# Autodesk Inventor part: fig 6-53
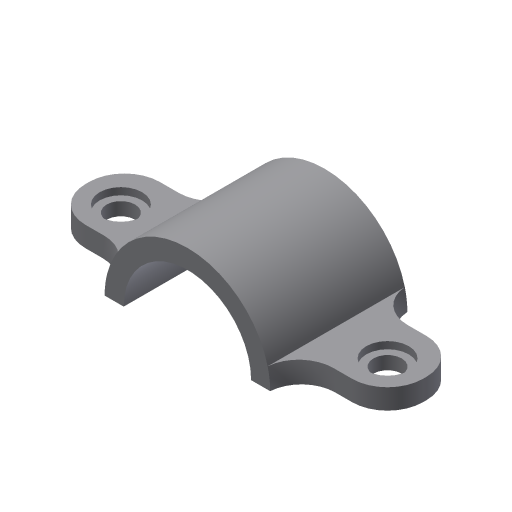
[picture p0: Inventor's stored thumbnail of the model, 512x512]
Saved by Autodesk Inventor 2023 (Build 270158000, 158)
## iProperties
Created: 2004-05
Part Number: fig 6-53
Document SubType Name: Modeling
Designer: CADCIM Technologies
Manufacturer: Standard
Standards Organization: Custom
Density: 1 g/cm^3
Material: Generic
Appearance: Default
Author: CADCIM Technologies
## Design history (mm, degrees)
node "Sketch1"
sketch "Sketch2"
  geometry: L1 (23.378, 0)-(17.996, 0); L2 (-17.996, 0)-(-23.378, 0); A1 r 23.378 centre (0, 0) between (23.378, 0) and (-23.378, 0); A2 r 17.996 centre (0, 0) between (17.996, 0) and (-17.996, 0)
  constraints: 4 end point, 4 point on circle, 2 centre point, 1 collinear, 1 horizontal
extrude "Extrusion1" new body sketch "Sketch2" stored distance "d0" = 38.75; taper "d1" = 0 deg
sketch "Sketch3"
  geometry: L1 (23.378, 0)-(17.996, 0); L2 (-17.996, 0)-(-23.378, 0) reference; L3 (-23.378, 0)-(-47.662, 0); L4 (-47.662, 0)-(-47.662, 5.722); L5 (-47.662, 5.722)-(-22.667, 5.722); A1 r 17.996 centre (0, 0) between (17.996, 0) and (-17.996, 0) reference; A2 r 23.378 centre (0, 0) between (23.378, 0) and (-23.378, 0) reference; 1 further point
  constraints: 10 end point, 5 point on circle, 2 centre point, 1 collinear, 1 horizontal, 1 midpoint, 1 parallel, 1 perpendicular, 3 other
extrude "Extrusion2" join sketch "Sketch3" stored distance "d2" = 21; taper "d3" = 0 deg
fillet "Fillet1" dims "d4" = 10
hole "Hole1" diameter "d7" = 8; stored, may be unused: countersink angle "d11" = 90 deg, drill point angle "d13" = 118 deg; dims "d5" = 10, "d6" = 10, "d8" = 6, "d9" = 12, "d10" = 2, "d12" = 12
fillet "Fillet2" dims "d14" = 9.5
mirror "Mirror1"
body "Solid1"
